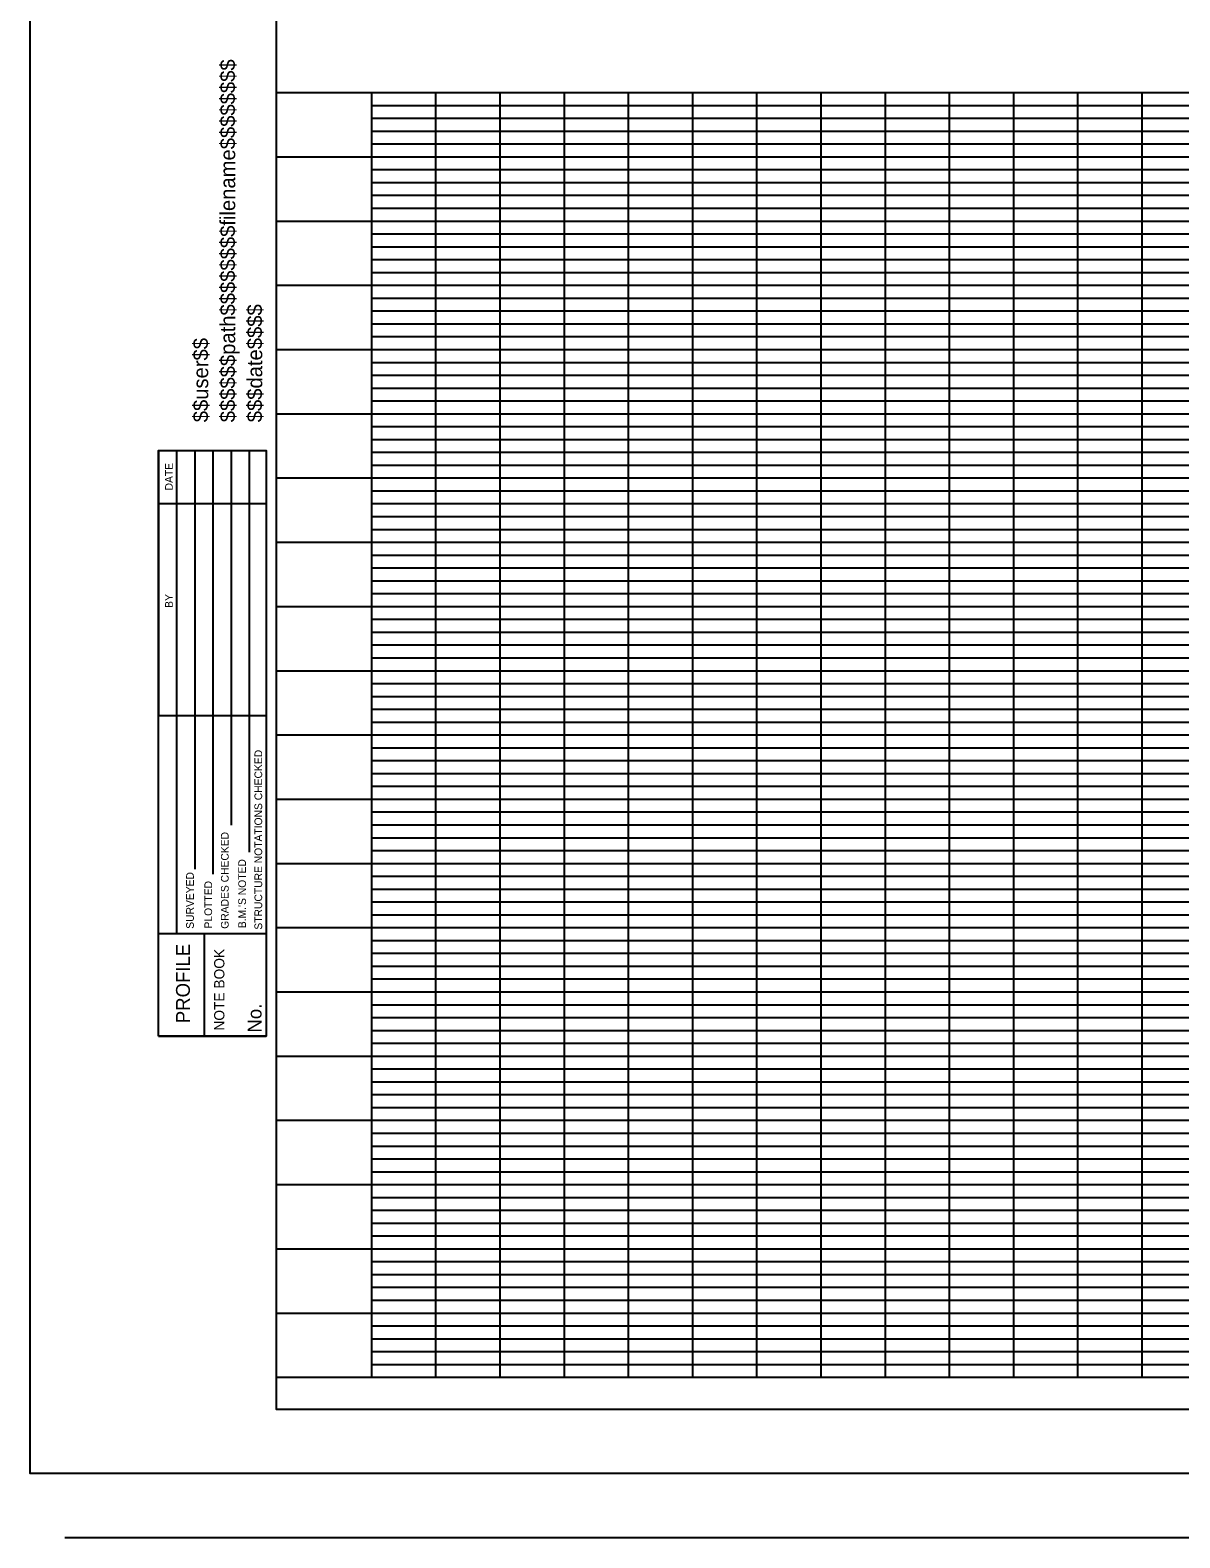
# Model space of a CAD drawing. Extents: x -183 to 1613, y -563 to 588.
# Drawn here: x -183 to 265, y -563 to 24 of the extents above; entities that cross this region are included whole.
import ezdxf

# ---------------------------------------------------------------- set-up
doc = ezdxf.new("R2010")
doc.units = 0
for name, color, linetype in [('RD_SHT_Bndy', 7, 'Continuous'), ('RD_SHT_ID', 7, 'Continuous'), ('RD_SHT_IplotShp', 7, 'Continuous'), ('RD_SHT_MjGrid', 7, 'Continuous'), ('RD_SHT_MnGrid', 7, 'Continuous'), ('RD_SHT_SubGrid', 7, 'Continuous'), ('RD_SHT_TX', 7, 'Continuous')]:
    doc.layers.add(name, color=color, linetype=linetype)

msp = doc.modelspace()

# ---------------------------------------------------------------- linework, layer by layer
at = {"layer": 'RD_SHT_Bndy'}
for p, q in [((-87, 0), (1588, 0)), ((-50, 0), (-50, -500)), ((-132.95, -139.3), (-132.95, -242.5)), ((-125.85, -139.3), (-125.85, -327.25)), ((-118.8, -139.3), (-118.8, -302.2)), ((-111.7, -139.3), (-111.7, -304.2)), ((-104.65, -139.3), (-104.65, -285.1)), ((-97.55, -139.3), (-97.55, -295.65)), ((-132.95, -159.95), (-90.95, -159.95)), ((-132.95, -242.5), (-90.95, -242.5)), ((-132.95, -327.3), (-90.95, -327.3)), ((-132.95, -367.3), (-132.95, -327.3)), ((-114.95, -367.3), (-114.95, -327.3)), ((-132.95, -367.3), (-90.95, -367.3)), ((-87, -500), (1588, -500)), ((1590.65, -537.5), (-169.35, -537.5)), ((1590.65, -562.5), (-169.35, -562.5))]:
    msp.add_line(p, q, dxfattribs=at)
for points in [[(-87, 537.5), (1588, 537.5), (1588, -512.5), (-87, -512.5)], [(-132.95, -367.3), (-132.95, -139.3), (-90.95, -139.3), (-90.95, -367.3)]]:
    msp.add_lwpolyline(points, close=True, dxfattribs=at)
at = {"layer": 'RD_SHT_IplotShp'}
msp.add_lwpolyline([(-182.9, 562.5), (1613, 562.5), (1613, -537.5), (-182.9, -537.5)], close=True, dxfattribs=at)
at = {"layer": 'RD_SHT_MjGrid'}
for p, q in [((0, 0), (0, -500)), ((50, 0), (50, -500)), ((100, 0), (100, -500)), ((150, 0), (150, -500)), ((200, 0), (200, -500)), ((250, 0), (250, -500)), ((-87, -50), (650, -50)), ((-87, -100), (1588, -100)), ((-87, -150), (1588, -150)), ((-87, -200), (1588, -200)), ((-87, -250), (1588, -250)), ((-87, -300), (1588, -300)), ((-87, -350), (1588, -350)), ((-87, -400), (1588, -400)), ((-87, -450), (1588, -450))]:
    msp.add_line(p, q, dxfattribs=at)
at = {"layer": 'RD_SHT_MnGrid'}
for p, q in [((-25, 0), (-25, -500)), ((25, 0), (25, -500)), ((75, 0), (75, -500)), ((125, 0), (125, -500)), ((175, 0), (175, -500)), ((225, 0), (225, -500)), ((-87, -25), (650, -25)), ((-87, -75), (650, -75)), ((-87, -125), (1588, -125)), ((-87, -175), (1588, -175)), ((-87, -225), (1588, -225)), ((-87, -275), (1588, -275)), ((-87, -325), (1588, -325)), ((-87, -375), (1588, -375)), ((-87, -425), (1588, -425)), ((-87, -475), (1588, -475))]:
    msp.add_line(p, q, dxfattribs=at)
at = {"layer": 'RD_SHT_SubGrid'}
for p, q in [((-49.95, -5), (650, -5)), ((-49.95, -10), (650, -10)), ((-49.95, -15), (650, -15)), ((-49.9, -20), (650, -20)), ((-49.95, -30), (650, -30)), ((-49.95, -35), (650, -35)), ((-49.95, -40), (650, -40)), ((-49.95, -45), (650, -45)), ((-49.95, -55), (650, -55)), ((-49.95, -60), (650, -60)), ((-49.95, -65), (650, -65)), ((-49.95, -70), (650, -70)), ((-49.95, -80), (650, -80)), ((-49.95, -85), (650, -85)), ((-49.95, -90), (650, -90)), ((-49.95, -95), (650, -95)), ((-49.95, -105), (1548.75, -105)), ((-49.95, -110), (1549.25, -110)), ((-49.95, -115), (1548.75, -115)), ((-49.9, -120), (1549.8, -120)), ((-49.95, -130), (1549.25, -130)), ((-49.95, -135), (1549.25, -135)), ((-49.95, -140), (1549.25, -140)), ((-49.95, -145), (1549.25, -145)), ((-49.85, -155), (1548.75, -155)), ((-49.85, -160), (1548.75, -160)), ((-49.9, -165), (1549.25, -165)), ((-49.9, -170), (1549.25, -170)), ((-49.95, -180), (1549.25, -180)), ((-49.95, -185), (1549.25, -185)), ((-49.95, -190), (1548.75, -190)), ((-49.95, -195), (1549.25, -195)), ((-49.95, -195), (1549.25, -195)), ((-49.95, -205), (1549.8, -205)), ((-49.95, -210), (1549.8, -210)), ((-49.95, -215), (1549.8, -215)), ((-49.95, -220), (1549.8, -220)), ((-49.95, -230), (1549.8, -230)), ((-49.95, -235), (1549.8, -235)), ((-49.95, -240), (1549.8, -240)), ((-49.95, -245), (1549.8, -245)), ((-49.95, -255), (1549.85, -255)), ((-49.95, -260), (1549.85, -260)), ((-49.95, -265), (1549.85, -265)), ((-49.95, -270), (1549.85, -270)), ((-49.95, -280), (1549.85, -280)), ((-49.95, -285), (1549.85, -285)), ((-49.95, -290), (1549.85, -290)), ((-49.95, -295), (1549.85, -295)), ((-49.95, -305), (1549.85, -305)), ((-49.95, -310), (1549.85, -310)), ((-49.95, -315), (1549.85, -315)), ((-49.95, -320), (1549.85, -320)), ((-49.95, -330), (1549.85, -330)), ((-49.9, -330), (1549.85, -330)), ((-49.95, -335), (1549.85, -335)), ((-49.9, -340), (1549.6, -340)), ((-49.9, -345), (1549.6, -345)), ((-49.9, -355), (1549.8, -355)), ((-49.95, -360), (1549.95, -360)), ((-49.95, -365), (1549.95, -365)), ((-49.9, -370), (1549.95, -370)), ((-49.95, -380), (1549.95, -380)), ((-49.95, -385), (1549.95, -385)), ((-49.95, -390), (1549.95, -390)), ((-49.9, -395), (1549.95, -395)), ((-49.95, -405), (1549.95, -405)), ((-49.95, -410), (1549.95, -410)), ((-49.95, -415), (1549.95, -415)), ((-49.95, -420), (1549.85, -420)), ((-49.9, -430), (1549.6, -430)), ((-49.95, -435), (1549.85, -435)), ((-49.95, -440), (1549.85, -440)), ((-49.95, -445), (1549.85, -445)), ((-49.85, -455), (1549.85, -455)), ((-49.95, -460), (1549.85, -460)), ((-49.95, -465), (1549.85, -465)), ((-49.95, -470), (1549.85, -470)), ((-49.85, -480), (1549.85, -480)), ((-49.85, -485), (1549.85, -485)), ((-49.85, -490), (1549.85, -490)), ((-49.85, -495), (1549.85, -495))]:
    msp.add_line(p, q, dxfattribs=at)

# ---------------------------------------------------------------- texts
at = {"layer": 'RD_SHT_ID'}
for s, p in [('$$$$$$path$$$$$$$$filename$$$$$$$$', (-103.05, -128.32)), ('$$$date$$$$', (-92.52, -128.32)), ('$$user$$', (-113.57, -128.32))]:
    msp.add_text(s, height=5.88, rotation=90, dxfattribs=at).set_placement(p)
at = {"layer": 'RD_SHT_TX'}
for s, height, p in [('DATE', 3, (-127.35, -154.85)), ('BY', 3, (-127.35, -200.55)), ('STRUCTURE NOTATIONS CHECKED', 3, (-92.55, -325.8)), ('GRADES CHECKED', 3, (-105.6, -325.45)), ("B.M.'S NOTED", 3, (-98.85, -325.2)), ('SURVEYED', 3, (-119.15, -325.45)), ('PLOTTED', 3, (-112.05, -325.35)), ('PROFILE', 5.4, (-120.7, -362.2)), ('NOTE BOOK', 4, (-107.25, -365.08)), ('No.', 5.4, (-92.8, -365.85))]:
    msp.add_text(s, height=height, rotation=90, dxfattribs=at).set_placement(p)

doc.saveas('drawing.dxf')
